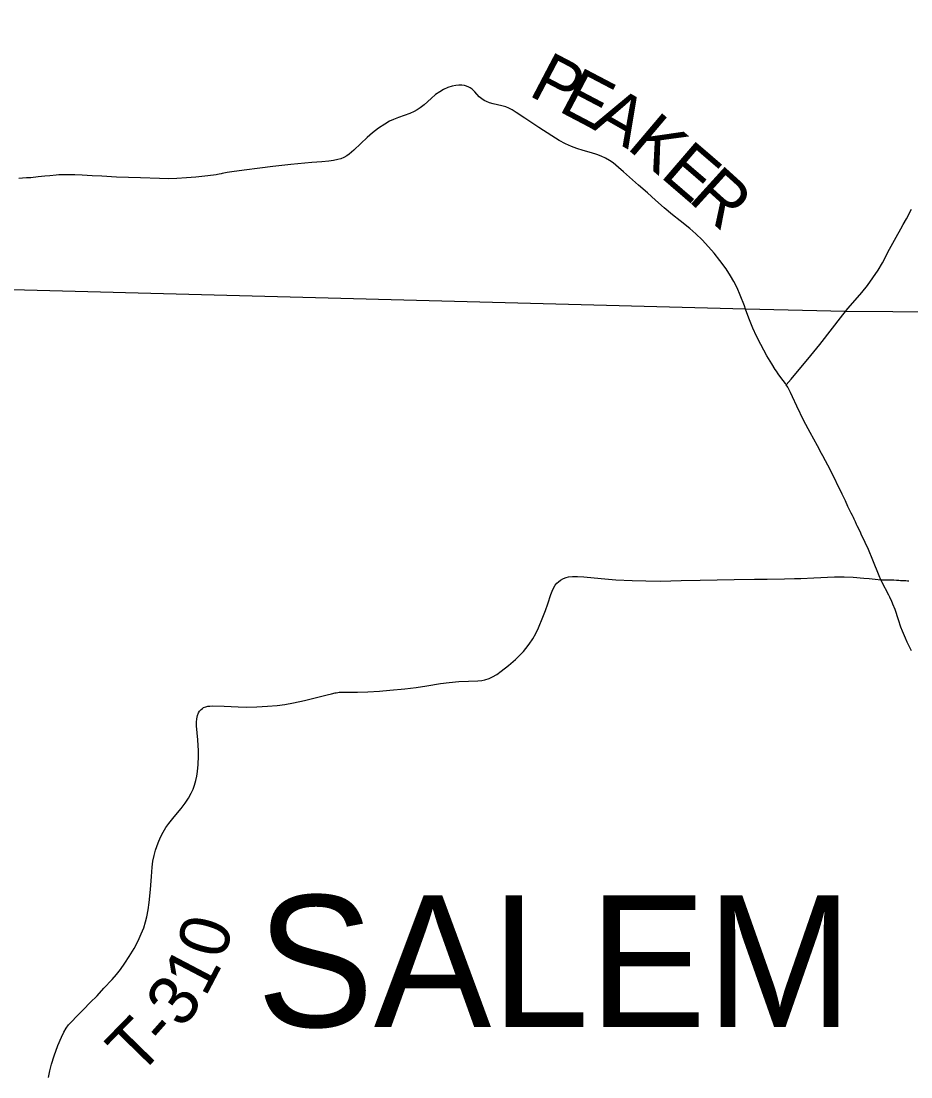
# Model space of a CAD drawing. Extents: x -10.5 to 40.6, y -3.2 to 22.
# Drawn here: x -9.528 to -8.513, y 15.152 to 16.355 of the extents above; entities that cross this region are included whole.
import ezdxf

# ---------------------------------------------------------------- set-up
doc = ezdxf.new("R2010")
doc.units = 0
for name, color, linetype in [('GM_X_Township_Road', 7, 'Continuous'), ('GM_X_Township_Road_Text', 7, 'Continuous'), ('GM_X_Township_Text', 7, 'Continuous')]:
    doc.layers.add(name, color=color, linetype=linetype)

msp = doc.modelspace()

# ---------------------------------------------------------------- linework, layer by layer
at = {"layer": 'GM_X_Township_Road'}
for points in [[(-8.7015, 16.027), (-8.7028, 16.0308), (-8.7075, 16.043), (-8.7112, 16.0515), (-8.7149, 16.0587), (-8.7187, 16.0651), (-8.7238, 16.0729), (-8.7307, 16.0824), (-8.7372, 16.0907), (-8.7437, 16.0982), (-8.7509, 16.1059), (-8.7581, 16.1128), (-8.765, 16.1189), (-8.7763, 16.1277), (-8.785, 16.1347), (-8.7945, 16.1427), (-8.8042, 16.1514), (-8.8135, 16.1595), (-8.8238, 16.1684), (-8.8408, 16.1837), (-8.8465, 16.1886), (-8.8527, 16.1938), (-8.8568, 16.1966), (-8.8611, 16.1991), (-8.8661, 16.2015), (-8.8713, 16.2035), (-8.8772, 16.2054), (-8.8867, 16.208), (-8.8938, 16.2102), (-8.9002, 16.2126), (-8.907, 16.2157), (-8.9141, 16.2195), (-8.9226, 16.2246), (-8.9372, 16.234), (-8.9532, 16.2447), (-8.963, 16.2513), (-8.9677, 16.2543), (-8.9715, 16.2563), (-8.975, 16.2576), (-8.9797, 16.259), (-8.9894, 16.2612), (-8.9936, 16.2624), (-8.9971, 16.2637), (-8.9998, 16.2651), (-9.0024, 16.2669), (-9.0052, 16.2693), (-9.0104, 16.2747), (-9.0135, 16.2777), (-9.0155, 16.2792), (-9.0171, 16.28), (-9.0199, 16.2812), (-9.0222, 16.282), (-9.0253, 16.2825), (-9.0284, 16.2826), (-9.0321, 16.2822), (-9.0363, 16.2812), (-9.041, 16.2796), (-9.0461, 16.2773), (-9.0504, 16.2748), (-9.055, 16.2716), (-9.0602, 16.2672), (-9.0681, 16.2601), (-9.0725, 16.2567), (-9.0761, 16.2543), (-9.0794, 16.2525), (-9.0845, 16.2502), (-9.0909, 16.2478), (-9.0972, 16.2456), (-9.103, 16.2434), (-9.1075, 16.2412), (-9.1129, 16.2381), (-9.1201, 16.2333), (-9.1271, 16.2281), (-9.1332, 16.2229), (-9.1404, 16.216), (-9.1484, 16.2082), (-9.1535, 16.2038), (-9.1564, 16.2017), (-9.1596, 16.1999), (-9.163, 16.1985), (-9.1666, 16.1975), (-9.1715, 16.1966), (-9.177, 16.1959), (-9.185, 16.1951), (-9.1962, 16.1941), (-9.2203, 16.1918), (-9.2407, 16.1896), (-9.2555, 16.1878), (-9.2733, 16.1854), (-9.2874, 16.1836), (-9.2929, 16.1827), (-9.2967, 16.1822), (-9.2984, 16.1818), (-9.2997, 16.1815), (-9.3019, 16.181), (-9.3037, 16.1806), (-9.3053, 16.1803), (-9.3149, 16.1789), (-9.3284, 16.1774), (-9.339, 16.1766), (-9.3501, 16.1759), (-9.3601, 16.1758), (-9.37, 16.176), (-9.3916, 16.1769), (-9.4189, 16.1776), (-9.4357, 16.1785), (-9.4468, 16.1791), (-9.458, 16.1797), (-9.4667, 16.18), (-9.4797, 16.18), (-9.4847, 16.18), (-9.4878, 16.1798), (-9.4952, 16.1792), (-9.5009, 16.1787), (-9.5085, 16.1778), (-9.5167, 16.1769), (-9.5215, 16.1766), (-9.5263, 16.1763), (-9.5305, 16.1759)], [(-8.5877, 16.0242), (-8.5847, 16.0279), (-8.5765, 16.0371), (-8.5688, 16.0459), (-8.5623, 16.0541), (-8.5562, 16.0626), (-8.5504, 16.0715), (-8.5454, 16.08), (-8.5372, 16.0953), (-8.5298, 16.109), (-8.5243, 16.1187), (-8.5216, 16.1235), (-8.518, 16.1299), (-8.5122, 16.1409)], [(-8.6551, 15.9409), (-8.656, 15.9423), (-8.6613, 15.9492), (-8.6642, 15.9532), (-8.6663, 15.9563), (-8.6677, 15.9583), (-8.6717, 15.9646), (-8.6771, 15.9737), (-8.6843, 15.9868), (-8.689, 15.9962), (-8.6931, 16.0052), (-8.6978, 16.0168), (-8.7015, 16.027)], [(-8.6551, 15.9409), (-8.6497, 15.9473), (-8.6405, 15.9583), (-8.6306, 15.9701), (-8.6168, 15.9869), (-8.5906, 16.0207), (-8.5877, 16.0242)], [(-8.5472, 15.7186), (-8.5493, 15.7231), (-8.5563, 15.741), (-8.5614, 15.753), (-8.5651, 15.7609), (-8.5696, 15.7704), (-8.5706, 15.7726), (-8.5741, 15.7799), (-8.5749, 15.7816), (-8.5762, 15.7844), (-8.5777, 15.7877), (-8.5785, 15.7894), (-8.5795, 15.7917), (-8.5809, 15.7944), (-8.5847, 15.8021), (-8.5876, 15.8083), (-8.5914, 15.8161), (-8.6048, 15.8433), (-8.6135, 15.8597), (-8.6164, 15.8652), (-8.6181, 15.8685), (-8.6196, 15.8712), (-8.6237, 15.8789), (-8.6279, 15.8865), (-8.6349, 15.8996), (-8.643, 15.9163), (-8.6479, 15.927), (-8.6502, 15.9321), (-8.6533, 15.9382), (-8.6551, 15.9409)], [(-9.4967, 15.1511), (-9.4952, 15.1584), (-9.4932, 15.1662), (-9.4901, 15.1756), (-9.4859, 15.1873), (-9.4818, 15.197), (-9.4791, 15.2026), (-9.4763, 15.2074), (-9.4737, 15.2109), (-9.4704, 15.2146), (-9.4642, 15.2209), (-9.4565, 15.2287), (-9.449, 15.2364), (-9.4412, 15.2442), (-9.4334, 15.2529), (-9.4241, 15.2629), (-9.4191, 15.2684), (-9.4145, 15.2742), (-9.4094, 15.2812), (-9.4044, 15.2891), (-9.399, 15.2982), (-9.3944, 15.307), (-9.3907, 15.3148), (-9.388, 15.3218), (-9.3859, 15.3283), (-9.3844, 15.3343), (-9.3828, 15.3421), (-9.3816, 15.3507), (-9.3802, 15.3655), (-9.3792, 15.3803), (-9.3784, 15.3908), (-9.3774, 15.3975), (-9.376, 15.4041), (-9.3744, 15.41), (-9.3714, 15.4187), (-9.3688, 15.4249), (-9.3658, 15.4309), (-9.3626, 15.4361), (-9.3594, 15.4407), (-9.3531, 15.4483), (-9.3452, 15.4578), (-9.3407, 15.4637), (-9.337, 15.4694), (-9.3337, 15.4753), (-9.3316, 15.4798), (-9.3299, 15.4844), (-9.3284, 15.4896), (-9.3275, 15.4944), (-9.3266, 15.4999), (-9.3258, 15.508), (-9.3253, 15.5173), (-9.3254, 15.5235), (-9.3262, 15.5359), (-9.3277, 15.552), (-9.3278, 15.554), (-9.3277, 15.5563), (-9.3273, 15.56), (-9.3265, 15.5637), (-9.3254, 15.5666), (-9.3242, 15.5687), (-9.3226, 15.5706), (-9.3211, 15.5718), (-9.3196, 15.5728), (-9.3173, 15.5737), (-9.3147, 15.5744), (-9.3124, 15.5745), (-9.3099, 15.5746), (-9.2963, 15.5743), (-9.2883, 15.574), (-9.2802, 15.5735), (-9.2709, 15.5733), (-9.2591, 15.5735), (-9.2467, 15.5742), (-9.2356, 15.5751), (-9.227, 15.5763), (-9.2172, 15.5781), (-9.2045, 15.5809), (-9.1894, 15.5847), (-9.1786, 15.5874), (-9.1737, 15.5885), (-9.1696, 15.5894), (-9.1683, 15.5897), (-9.1665, 15.5901), (-9.1652, 15.5902), (-9.1638, 15.5902), (-9.1624, 15.5903), (-9.1538, 15.5902), (-9.144, 15.5902), (-9.1322, 15.5907), (-9.1192, 15.5916), (-9.1074, 15.5925), (-9.0901, 15.5941), (-9.0772, 15.5957), (-9.0649, 15.5977), (-9.0496, 15.6001), (-9.0397, 15.6014), (-9.0286, 15.6024), (-9.0174, 15.603), (-9.0068, 15.6034), (-9.0025, 15.6038), (-8.9989, 15.6045), (-8.9941, 15.6061), (-8.9902, 15.6078), (-8.9853, 15.6106), (-8.9802, 15.6141), (-8.972, 15.6206), (-8.9641, 15.6276), (-8.9574, 15.6341), (-8.9548, 15.6368), (-8.952, 15.6401), (-8.9482, 15.6449), (-8.9441, 15.6512), (-8.9408, 15.6571), (-8.9377, 15.6638), (-8.9328, 15.6758), (-8.9299, 15.6834), (-8.9272, 15.691), (-8.9236, 15.7016), (-8.9221, 15.7056), (-8.9207, 15.7091), (-8.9187, 15.7122), (-8.9167, 15.7146), (-8.9149, 15.7163), (-8.9125, 15.7182), (-8.9092, 15.72), (-8.9063, 15.721), (-8.9033, 15.7218), (-8.8989, 15.7223), (-8.8934, 15.7224), (-8.8859, 15.7219), (-8.8661, 15.7199), (-8.8494, 15.7186), (-8.8308, 15.7176), (-8.8153, 15.7171), (-8.7985, 15.717), (-8.7749, 15.7175), (-8.7532, 15.7181), (-8.7147, 15.7188), (-8.6912, 15.7192), (-8.6769, 15.7193), (-8.657, 15.7194), (-8.6458, 15.7198), (-8.6384, 15.72), (-8.6235, 15.7206), (-8.6, 15.7218), (-8.5889, 15.7218), (-8.5789, 15.7214), (-8.5668, 15.7205), (-8.5606, 15.72), (-8.5536, 15.7193), (-8.5472, 15.7186)], [(-8.5472, 15.7186), (-8.5436, 15.7185), (-8.5399, 15.7184), (-8.5358, 15.7183), (-8.5323, 15.7183), (-8.5293, 15.7181), (-8.5268, 15.718), (-8.5248, 15.7178), (-8.5232, 15.7178), (-8.521, 15.7176), (-8.5189, 15.7175), (-8.517, 15.7174), (-8.5153, 15.7173)], [(-8.5124, 15.6375), (-8.5136, 15.6397), (-8.5145, 15.642), (-8.5172, 15.6474), (-8.5192, 15.6519), (-8.5227, 15.6598), (-8.5245, 15.6644), (-8.5271, 15.6727), (-8.531, 15.6845), (-8.5335, 15.6908), (-8.534, 15.692), (-8.5347, 15.6937), (-8.537, 15.6988), (-8.538, 15.701), (-8.5462, 15.7163), (-8.5472, 15.7186)]]:
    msp.add_lwpolyline(points, dxfattribs=at)
at = {"layer": 'GM_X_Township_Text'}
msp.add_lwpolyline([(-10.5445, 19.4241), (-10.5445, 16.0741), (-10.3151, 16.0685), (-10.1031, 16.0664), (-9.5534, 16.0497), (-8.7017, 16.0275), (-8.5879, 16.0247), (-8.2615, 16.0223), (-8.2451, 17.3912), (-8.2441, 17.4134)], dxfattribs=at)

# ---------------------------------------------------------------- texts
at = {"layer": 'GM_X_Township_Road_Text'}
for s, rotation, p in [('P', 332.2959, (-8.9505, 16.2715)), ('E', 332.2943, (-8.9166, 16.2537)), ('A', 330.2777, (-8.8794, 16.2341)), ('K', 319.7579, (-8.8382, 16.2109)), ('E', 319.3132, (-8.8002, 16.1787)), ('R', 317.7775, (-8.7682, 16.1513)), ('0', 73.9283, (-9.2968, 15.2842)), ('1', 62.2811, (-9.3178, 15.2416)), ('3', 53.3153, (-9.3439, 15.2053)), ('T', 45.7152, (-9.3944, 15.1512)), ('-', 48.3401, (-9.3628, 15.1837))]:
    msp.add_text(s, height=0.0568, rotation=rotation, dxfattribs=at).set_placement(p)
at = {"layer": 'GM_X_Township_Text'}
msp.add_text('SALEM', height=0.15, rotation=0, dxfattribs=at).set_placement((-9.2592, 15.2087))

doc.saveas('drawing.dxf')
